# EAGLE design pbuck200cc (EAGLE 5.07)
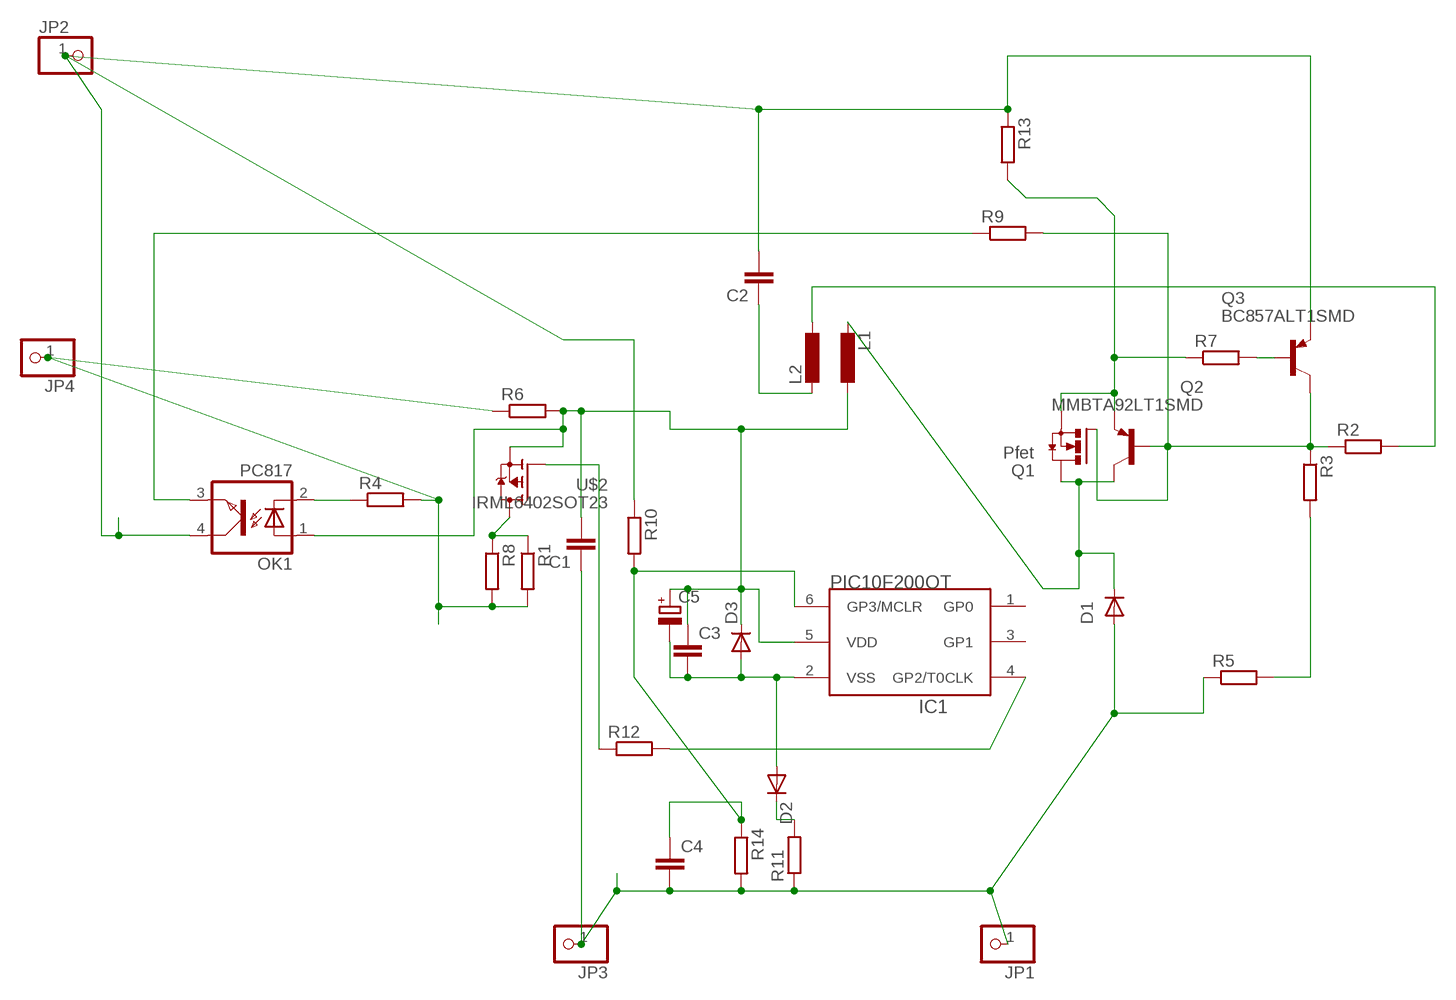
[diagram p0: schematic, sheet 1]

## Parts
C1  C-EU025-025X050  [C025-025X050]
C2  C-EUC0805  [C0805]
C3  C-EUC0805  [C0805]
C4  C-EUC1206  [C1206]
C5  CPOL-EUE2.5-5  [E2,5-5]
D1  DIODE-SMC  [SMC]
D2  DIODE-MINIMELF  [MINIMELF]
D3  DIODE-MINIMELF  [MINIMELF]
IC1  PIC10F200OT  [SOT23-6]
JP1  PINHD-1X11MM6  [1X1MM8]
JP2  PINHD-1X11MM6  [1X1MM8]
JP3  PINHD-1X11MM6  [1X1MM8]
JP4  PINHD-1X11MM6  [1X1MM8]
L1  L-EU0204/5  [0204/5]
L2  L-EU0207/10  [0207/10]
OK1  PC817  [DIL04]
Q1  Pfet  N-HEXFET_DPAK-  [TO252]
Q2  MMBTA92LT1SMD  [SOT23-BEC]
Q3  BC857ALT1SMD  [SOT23-BEC]
R1  R-EU_R2010  [R2010]
R2  R-EU_R0805  [R0805]
R3  R-EU_R1206  [R1206]
R4  R-EU_R0805  [R0805]
R5  R-EU_R1206  [R1206]
R6  R-EU_R0805  [R0805]
R7  R-EU_R1206  [R1206]
R8  R-EU_R2512  [R2512]
R9  R-EU_R0805  [R0805]
R10  R-EU_R0805  [R0805]
R11  R-EU_R1206  [R1206]
R12  R-EU_R0805  [R0805]
R13  R-EU_R1206  [R1206]
R14  R-EU_R0805  [R0805]
U$2  IRML6402SOT23  [SOT23]

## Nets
-: C1.1 C4.2 D1.A JP1.1 JP3.1 R5.1 R11.1 R14.2
B1C2: OK1.3(EMIT) R9.1
C1: D1.C L1.2 Q1.3(D) Q2.C
DR+: R1.1 R8.1 U$2.3(D)
EB: Q1.2(S) Q2.E R7.1 R13.2
N$1: R3.2 R5.2
N$2: Q1.1(G) Q2.B Q3.C R2.1 R3.1 R9.2
N$3: Q3.B R7.2
N$4: L2.1 R2.2
N$5: C3.2 C5.- D2.A D3.A IC1.2(VSS)
N$6: C2.1 L2.2
N$8: OK1.2(C) R4.1
N$9: IC1.4(GP2/T0CLK) R12.2
N$10: D2.C R11.2
N$12: C4.1 IC1.6(GP3/MCLR) R10.2 R14.1
N$13: R12.1 U$2.1(G)
OUT: JP4.1 R1.2 R4.2 R6.1 R8.2
OUT+: C1.2 C3.1 C5.+ D3.C IC1.5(VDD) L1.1 OK1.1(A) R6.2 U$2.2(S)
VPLUS: C2.2 JP2.1 OK1.4(COL) Q3.E R10.1 R13.1
Unconnected: IC1.1(GP0) IC1.3(GP1)

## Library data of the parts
C1-C4 = rcl:C-EU: CAPACITOR, European symbol
C5 = rcl:CPOL-EU: POLARIZED CAPACITOR, European symbol
D1-D3 = diode:DIODE-: DIODE
IC1 = microchip-5:PIC10F20*: uPC nW 0,25/0,5k Program Flash memory
JP1-JP4 = pinhead:PINHD-1X1: PIN HEADER
L1 L2 = rcl:L-EU: INDUCTOR, European symbol
OK1 = optocoupler:PC817: SHARP OPTO COUPLER
Q1 = transistor-power:N-HEXFET_?-*: HEXFET® Power MOSFET
Q2 = transistor-pnp:MMBTA92*: PNP Transistror
Q3 = transistor-pnp:BC857*: PNP Transistror
R1-R14 = rcl:R-EU_: RESISTOR, European symbol
U$2 = transistor-fet:IRML6402

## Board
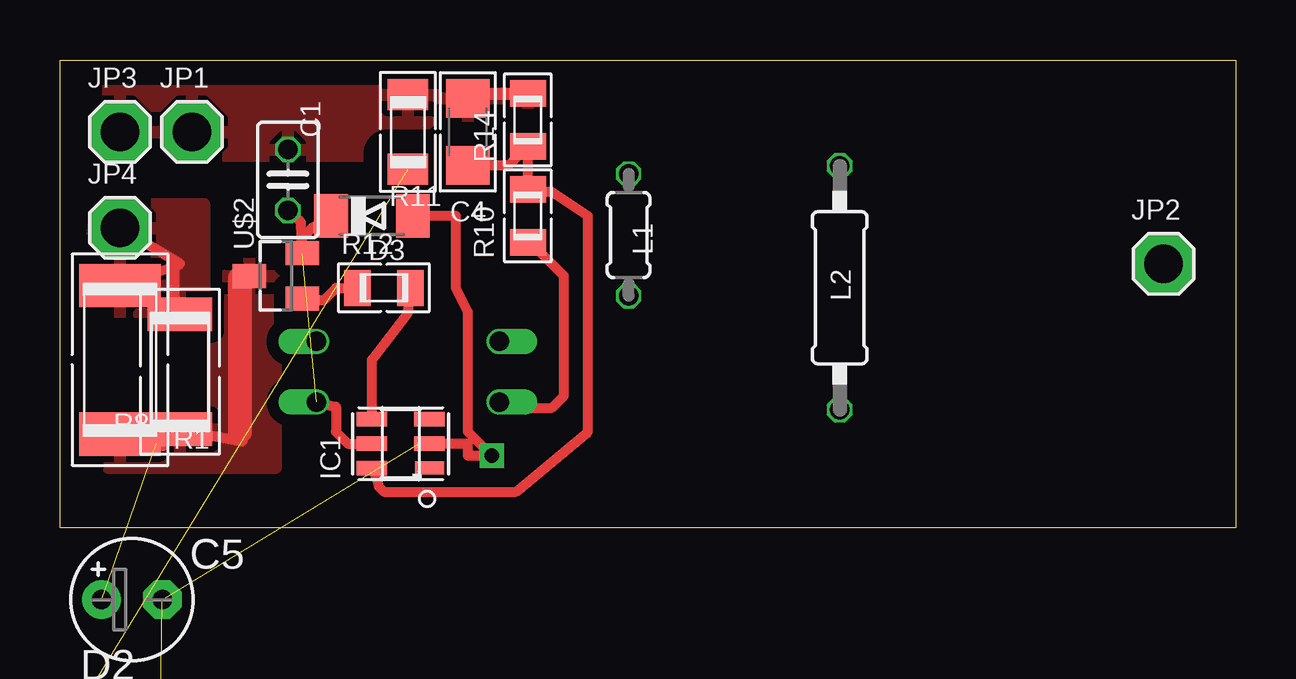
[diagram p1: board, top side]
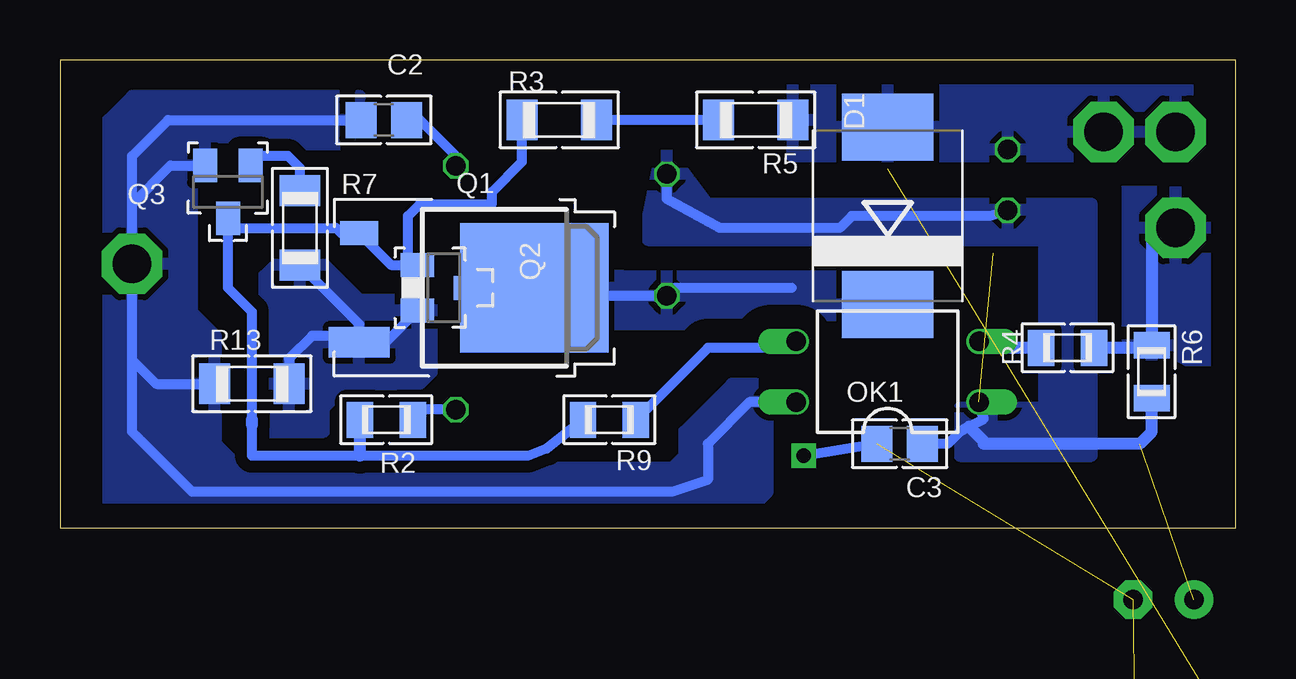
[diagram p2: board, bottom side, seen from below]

Size 49 x 19.5 mm. Coordinates in mm from the lower left corner, seen from the top.
Outline: 0,19.5 49,19.5 49,0 0,0 0,19.5
Copper layers (1*16): Top 0.035mm / dielectric 1.5mm / Bottom 0.035mm
Design rules "default *": minimum track width 10mil, minimum drill 20mil, track to track 8mil, track to pad 8mil, pad to pad 8mil, via to via 8mil, smd to smd 8mil, copper to edge 40mil, drill to drill 8mil, minimum pad ring 1mil, minimum via ring 8mil, stop-mask expansion 4mil, vias tented up to drill 0mil, thermal gap 10mil

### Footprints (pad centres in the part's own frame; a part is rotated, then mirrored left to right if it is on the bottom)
C025-025X050 = drill 0.813 octagon: 1 -1.27,0; 2 1.27,0
C0805 = smd 1.3 x 1.5: 1 -0.95,0; 2 0.95,0
C1206 = smd 1.6 x 1.8: 1 -1.4,0; 2 1.4,0
E2,5-5 = drill 0.813 pad 1.6 round: + -1.27,0 | drill 0.813 pad 1.6 octagon: - 1.27,0
SMC = smd 2.8 x 3.8: A 3.7,0; C -3.7,0
MINIMELF = smd 1.4 x 1.8: A 1.7,0; C -1.7,0
SOT23-6 = smd 0.55 x 1.2: 1 -1.016,-1.2 | smd 0.6 x 1.27: 2 0,-1.2; 3 1.016,-1.2; 4 1.016,1.2; 5 0,1.2; 6 -1.016,1.2
1X1MM8 = drill 1.6 pad 2.54 octagon: 1 0,0
0204/5 = drill 0.813 octagon: 1 -2.54,0; 2 2.54,0
0207/10 = drill 0.813 octagon: 1 -5.08,0; 2 5.08,0
DIL04 = drill 0.813 offset: 1 -1.27,-3.81; 2 1.27,-3.81; 3 1.27,3.81; 4 -1.27,3.81
TO252 = smd 1 x 1.6: 1 -2.28,-3.53 | smd 1.27 x 2.54: 2 2.28,-3.53 | smd 5.4 x 6.2: 3 0,3.77
SOT23-BEC = smd 1 x 1.4: B -0.95,-1.1; C 0,1.1; E 0.95,-1.1
R2010 = smd 1.4 x 2.7: 1 -2.4,0; 2 2.4,0
R0805 = smd 1.1 x 1.5: 1 -1.1,0; 2 1.1,0
R1206 = smd 1.3 x 1.7: 1 -1.55,0; 2 1.55,0
R2512 = smd 1.8 x 3.4: 1 -3.1,0; 2 3.1,0
SOT23 = smd 1 x 1.4: 1 -0.95,-1.1; 2 0.95,-1.1; 3 0,1.1

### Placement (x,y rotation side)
C1  9.5,14.5 270 top
C2  35.5,17 180 bottom
C3  14,3.5 180 bottom
C4  17,16.5 90 top
C5  3,-3 0 top
D1  14.5,13 90 bottom
D2  not placed on the board
D3  13,13 0 top
IC1  14.2,3.5 90 top
JP1  5.5,16.5 0 top
JP2  46,11 0 top
JP3  2.5,16.5 0 top
JP4  2.5,12.5 0 top
L1  23.7,12.2 270 top
L2  32.5,10 90 top
OK1  14.5,6.5 90 bottom
Q1  33,10 270 bottom
Q2  33,10 270 bottom
Q3  42,14 180 bottom
R1  5,6.5 90 top
R2  35.4,4.5 0 bottom
R3  28.19,17 0 bottom
R4  7,7.5 0 bottom
R5  20,17 180 bottom
R6  3.5,6.5 270 bottom
R7  39,12.5 90 bottom
R8  2.5,7 90 top
R9  26.1,4.5 180 bottom
R10  19.5,13 90 top
R11  14.5,16.5 270 top
R12  13.5,10 0 top
R13  41,6 0 bottom
R14  19.5,17 90 top
U$2  9,10.5 90 top

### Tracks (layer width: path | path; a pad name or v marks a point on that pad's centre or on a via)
-
  Top 0.5: R14.2 17.2,18.1 C4.2
  pour Bottom (isolate 1, rank 2): 2,18.5 18.5,18.5 18.5,15.5 2,15.5
  pour Top (isolate 1, rank 2): 2,18.5 20,18.5 20,15.5 2,15.5
B1C2
  Bottom 0.406: R9.1 22,7.5 19.58,7.5 OK1.3
C1
  Bottom 0.406: 18.5,10 23.36,10 L1.2 28.89,9.66 Q1.3 Q2.C
  pour Bottom (isolate 1, rank 2): 16,10.5 28,10.5 28,10 28,8.5 16,8.5 16,9
DR+
  Top 0.406: 7.5,10.4 U$2.3 | 7.5,4 7.6,3.6 R1.1 4.3,3.4 R8.1
  Top 1: 7.5,4 7.5,10.4
  pour Top (isolate 0.5, rank 2): 9,2.5 9,11 7,11 7,9.5 6.5,9.5 6.5,4 2,4.5 2,2.5
EB
  Bottom 0.406: R13.2 39.45,7.05 38.5,8 36.81,8 Q1.2 | Q1.2 35.43,7.72 Q2.E | Q1.2 36.53,8.48 R7.1
  pour Bottom (isolate 0.5, rank 2): 33.5,9.5 36.5,9.5 38,11 40,11 40.5,10.5 40.5,4 38,4 38,5 37,6 34,6 33.5,6.5
N$1
  Bottom 0.406: R5.2 R3.2
N$2
  Bottom 0.406: 41,4.5 41,9 42,10 Q3.C 41.6,12.5 37.5,12.5 37.28,12.28 Q1.1 35.2,10.95 Q2.B 34.5,11.35 34.5,13 34,13.5 31,13.5 31,14 29.74,15.26 R3.1 | R9.2 28.7,3.3 29.5,3 36.5,3 41,3 41,4.3
  Bottom 0.5: 41,4.3 41,4.5 | 36.5,3 R2.1
N$3
  Bottom 0.406: R7.2 39,15 39.5,15.5 40.65,15.5 Q3.B
N$4
  Bottom 0.406: L2.1 33.78,4.92 R2.2
N$5  (via drill 0.6)  (2 unrouted)
  Top 0.406: 14.7,13.15 D3.A 16.5,13 16.5,10 17,9 17,4 v18,3 17,3 17,3.5 IC1.2
  Bottom 0.406: C3.2 v18,3
N$6
  Bottom 0.406: L2.2 32.5,15.5 34,17 C2.1
N$8
  Bottom 0.5: R4.1 10.42,7.5 OK1.2
N$9
  Top 0.406: IC1.4 13,7 14.5,8.95 R12.2
N$10  (1 unrouted)
N$12
  Top 0.406: IC1.6 13.3,1.7 13.5,1.5 19,1.5 22,4 22,13 20.5,14 19.6,14 R10.2 R14.1 18.7,15.1 C4.1
N$13
  Top 0.406: R12.1 11.5,10 11,9.5 10.15,9.5 U$2.1
OUT
  Top 0.406: JP4.1 5,11 4.79,10.88 | 4.79,10.88 R8.2 | R1.2 4.79,9.61 4.79,10.88
  Bottom 0.5: JP4.1 3.5,12.5 R6.1 3.6,7.5 R4.2
  pour Bottom (isolate 1, rank 2): 1,14 5.5,14 5.5,7 1,7
  pour Top (isolate 0.5, rank 3): 1.5,13.5 6,13.5 6,9 1,9
OUT+  (2 unrouted)
  Top 0.406: C1.2 10.05,12.73 U$2.2 10.1,12.1 10.5,12.5 D3.C | IC1.5 12,3.5 11.5,4 11.5,5.04 OK1.1
  Bottom 0.406: L1.1 23.7,13.7 21.5,12.5 16.5,12.5 16,13 10.23,13 C1.2 | C3.1 12,3.5 11.5,4 11.11,4.21 10.5,4.54 OK1.1
  Bottom 0.5: R6.2 3.5,4 4,3.5 10.5,3.5 10.5,3.6 11.11,4.21
  pour Bottom (isolate 0.3): 6,13.5 22,13.5 23.5,15.5 24,15.5 24.5,13 24.5,12 8,12 8,5 11.5,5 11.5,3 6,3
VPLUS
  Top 0.406: R10.1 19.6,11.9 21,10.5 21,5.5 20.5,5 18.54,5 OK1.4
  Bottom 0.406: C2.2 44.5,17 46,15.5 46,13.5 | 46,13.5 JP2.1 46,7 | R13.1 45,6 46,7 | Q3.E 44.4,15.1 46,13.5 | OK1.4 20.27,5.23 22,3.5 22,2 23.5,1.5 43.5,1.5 46,4 46,7
  pour Bottom (isolate 0.5, rank 2): 36.5,18 46,18 47,17 47,1 20,1 19.5,1.5 19.5,5.5 20,6 21,6 23,4 23,3 23.5,2.5 41.5,2.5 42.5,3.5 42.5,8 43.5,9 43.5,15.5 43,16 37,16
